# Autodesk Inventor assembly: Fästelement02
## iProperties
Created: 2001-12
Part Number: Fästelement02
Document SubType Name: Assembly
Designer: Tobben
Control State: 0
Master: False
Checked Out: False
Shininess: 64.0
Length Units: 11269
Angle Units: 11279
Time Units: 11290
Mass Units: 11283
Length Display Precision: 3
Angle Display Precision: 2
Density: 0.0
Volumn: 0.0
Area: 0.0
PropertySet Name: Model Information
Author: Tobben
